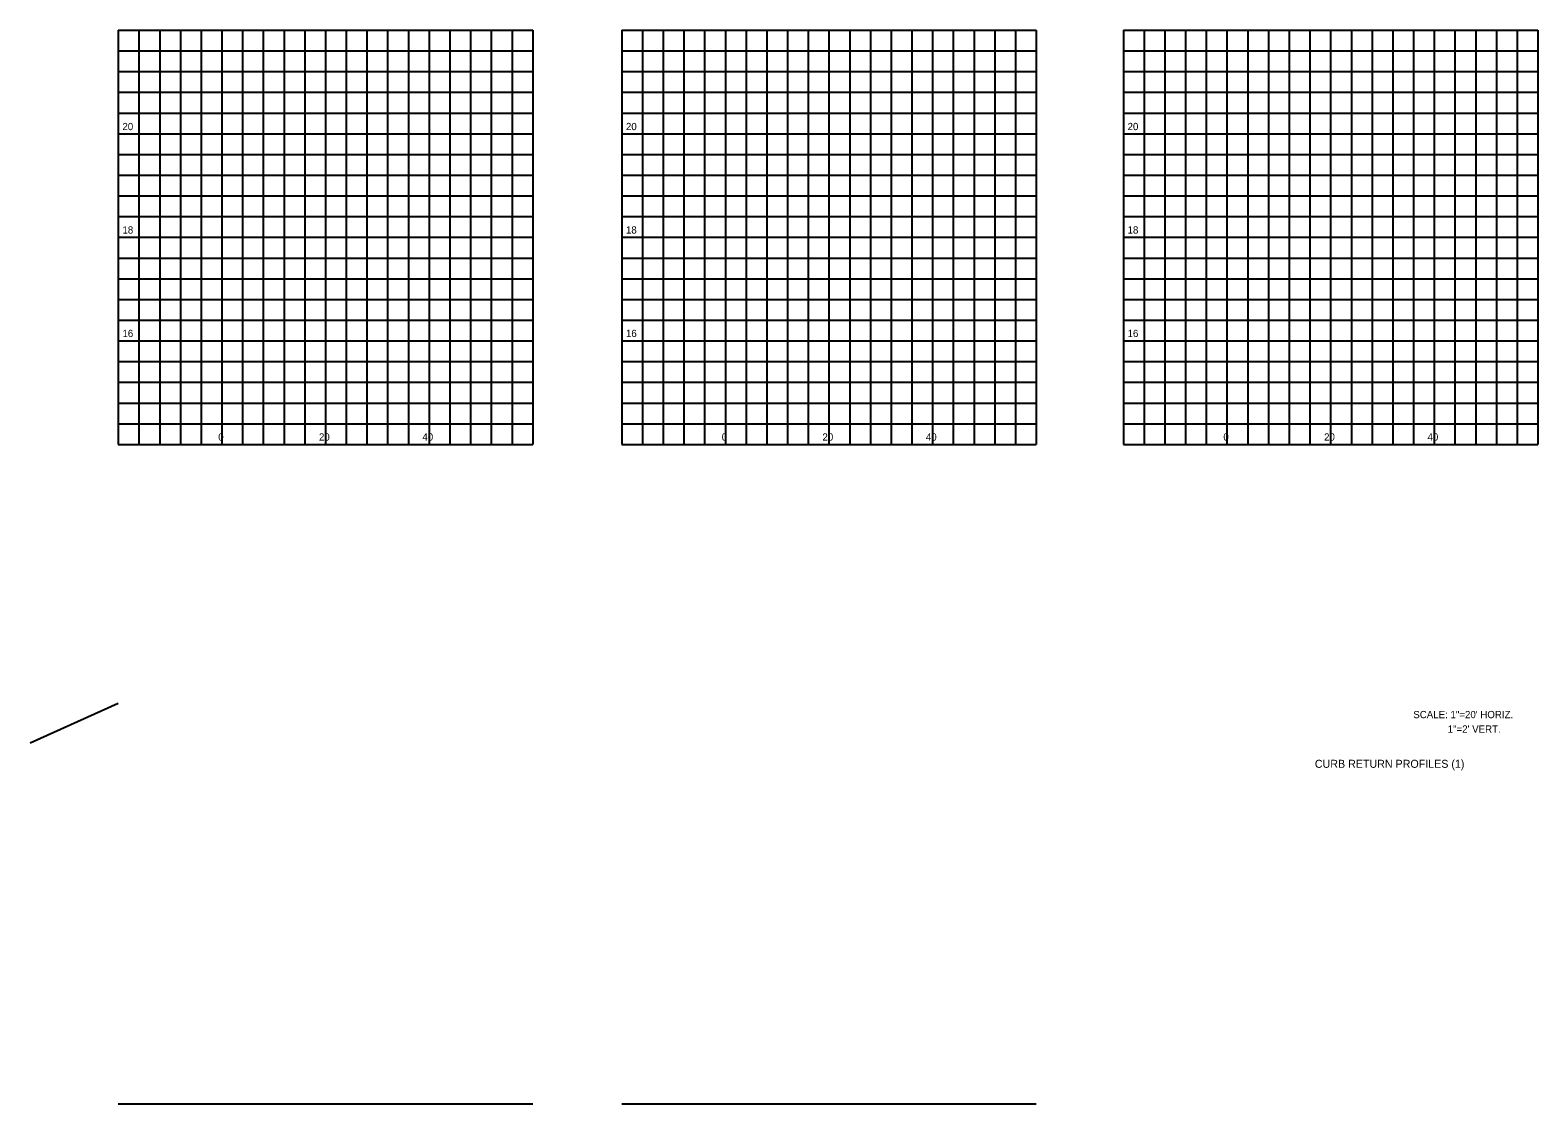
# Model space of a CAD drawing. Extents: x 127723 to 128378, y 21426 to 23736.
# Drawn here: x 127722.5 to 128013.5, y 23485.3 to 23692.7 of the extents above; entities that cross this region are included whole.
import ezdxf

# ---------------------------------------------------------------- set-up
doc = ezdxf.new("R2010")
doc.units = 0
for name, color, linetype in [('Default', 7, 'Continuous'), ('GroundCover', 7, 'Continuous'), ('Miscellaneous0', 7, 'Continuous'), ('SheetBorder_dp', 7, 'Continuous'), ('TextNotes', 7, 'Continuous')]:
    doc.layers.add(name, color=color, linetype=linetype)

msp = doc.modelspace()

# ---------------------------------------------------------------- linework, layer by layer
at = {"layer": 'Miscellaneous0'}
for p, q in [((127743.54, 23692.65), (127743.54, 23612.65)), ((127747.54, 23692.65), (127747.54, 23612.65)), ((127751.54, 23692.65), (127751.54, 23612.65)), ((127755.54, 23692.65), (127755.54, 23612.65)), ((127763.54, 23692.65), (127763.54, 23612.65)), ((127767.54, 23692.65), (127767.54, 23612.65)), ((127771.54, 23692.65), (127771.54, 23612.65)), ((127775.54, 23692.65), (127775.54, 23612.65)), ((127783.54, 23692.65), (127783.54, 23612.65)), ((127787.54, 23692.65), (127787.54, 23612.65)), ((127791.54, 23692.65), (127791.54, 23612.65)), ((127795.54, 23692.65), (127795.54, 23612.65)), ((127803.54, 23692.65), (127803.54, 23612.65)), ((127807.54, 23692.65), (127807.54, 23612.65)), ((127811.54, 23692.65), (127811.54, 23612.65)), ((127815.54, 23692.65), (127815.54, 23612.65)), ((127840.72, 23692.65), (127840.72, 23612.65)), ((127844.72, 23692.65), (127844.72, 23612.65)), ((127848.72, 23692.65), (127848.72, 23612.65)), ((127852.72, 23692.65), (127852.72, 23612.65)), ((127860.72, 23692.65), (127860.72, 23612.65)), ((127864.72, 23692.65), (127864.72, 23612.65)), ((127868.72, 23692.65), (127868.72, 23612.65)), ((127872.72, 23692.65), (127872.72, 23612.65)), ((127880.72, 23692.65), (127880.72, 23612.65)), ((127884.72, 23692.65), (127884.72, 23612.65)), ((127888.72, 23692.65), (127888.72, 23612.65)), ((127892.72, 23692.65), (127892.72, 23612.65)), ((127900.72, 23692.65), (127900.72, 23612.65)), ((127904.72, 23692.65), (127904.72, 23612.65)), ((127908.72, 23692.65), (127908.72, 23612.65)), ((127912.72, 23692.65), (127912.72, 23612.65)), ((127937.54, 23692.65), (127937.54, 23612.65)), ((127941.54, 23692.65), (127941.54, 23612.65)), ((127945.54, 23692.65), (127945.54, 23612.65)), ((127949.54, 23692.65), (127949.54, 23612.65)), ((127957.54, 23692.65), (127957.54, 23612.65)), ((127961.54, 23692.65), (127961.54, 23612.65)), ((127965.54, 23692.65), (127965.54, 23612.65)), ((127969.54, 23692.65), (127969.54, 23612.65)), ((127977.54, 23692.65), (127977.54, 23612.65)), ((127981.54, 23692.65), (127981.54, 23612.65)), ((127985.54, 23692.65), (127985.54, 23612.65)), ((127989.54, 23692.65), (127989.54, 23612.65)), ((127997.54, 23692.65), (127997.54, 23612.65)), ((128001.54, 23692.65), (128001.54, 23612.65)), ((128005.54, 23692.65), (128005.54, 23612.65)), ((128009.54, 23692.65), (128009.54, 23612.65)), ((127739.54, 23688.65), (127819.54, 23688.65)), ((127836.72, 23688.65), (127916.72, 23688.65)), ((127933.54, 23688.65), (128013.54, 23688.65)), ((127739.54, 23684.65), (127819.54, 23684.65)), ((127836.72, 23684.65), (127916.72, 23684.65)), ((127933.54, 23684.65), (128013.54, 23684.65)), ((127739.54, 23680.65), (127819.54, 23680.65)), ((127836.72, 23680.65), (127916.72, 23680.65)), ((127933.54, 23680.65), (128013.54, 23680.65)), ((127739.54, 23676.65), (127819.54, 23676.65)), ((127836.72, 23676.65), (127916.72, 23676.65)), ((127933.54, 23676.65), (128013.54, 23676.65)), ((127739.54, 23668.65), (127819.54, 23668.65)), ((127836.72, 23668.65), (127916.72, 23668.65)), ((127933.54, 23668.65), (128013.54, 23668.65)), ((127739.54, 23664.65), (127819.54, 23664.65)), ((127836.72, 23664.65), (127916.72, 23664.65)), ((127933.54, 23664.65), (128013.54, 23664.65)), ((127739.54, 23660.65), (127819.54, 23660.65)), ((127836.72, 23660.65), (127916.72, 23660.65)), ((127933.54, 23660.65), (128013.54, 23660.65)), ((127739.54, 23656.65), (127819.54, 23656.65)), ((127836.72, 23656.65), (127916.72, 23656.65)), ((127933.54, 23656.65), (128013.54, 23656.65)), ((127739.54, 23648.65), (127819.54, 23648.65)), ((127836.72, 23648.65), (127916.72, 23648.65)), ((127933.54, 23648.65), (128013.54, 23648.65)), ((127739.54, 23644.65), (127819.54, 23644.65)), ((127836.72, 23644.65), (127916.72, 23644.65)), ((127933.54, 23644.65), (128013.54, 23644.65)), ((127739.54, 23640.65), (127819.54, 23640.65)), ((127836.72, 23640.65), (127916.72, 23640.65)), ((127933.54, 23640.65), (128013.54, 23640.65)), ((127739.54, 23636.65), (127819.54, 23636.65)), ((127836.72, 23636.65), (127916.72, 23636.65)), ((127933.54, 23636.65), (128013.54, 23636.65)), ((127739.54, 23628.65), (127819.54, 23628.65)), ((127836.72, 23628.65), (127916.72, 23628.65)), ((127933.54, 23628.65), (128013.54, 23628.65)), ((127739.54, 23624.65), (127819.54, 23624.65)), ((127836.72, 23624.65), (127916.72, 23624.65)), ((127933.54, 23624.65), (128013.54, 23624.65)), ((127739.54, 23620.65), (127819.54, 23620.65)), ((127836.72, 23620.65), (127916.72, 23620.65)), ((127933.54, 23620.65), (128013.54, 23620.65)), ((127739.54, 23616.65), (127819.54, 23616.65)), ((127836.72, 23616.65), (127916.72, 23616.65)), ((127933.54, 23616.65), (128013.54, 23616.65))]:
    msp.add_line(p, q, dxfattribs=at)
at = {"layer": 'SheetBorder_dp'}
for p, q in [((127739.54, 23692.65), (127819.54, 23692.65)), ((127739.54, 23692.65), (127739.54, 23612.65)), ((127759.54, 23692.65), (127759.54, 23632.65)), ((127759.54, 23692.65), (127759.54, 23612.65)), ((127779.54, 23692.65), (127779.54, 23612.65)), ((127799.54, 23692.65), (127799.54, 23612.65)), ((127819.54, 23692.65), (127819.54, 23612.65)), ((127836.72, 23692.65), (127916.72, 23692.65)), ((127836.72, 23692.65), (127836.72, 23612.65)), ((127856.72, 23692.65), (127856.72, 23632.65)), ((127856.72, 23692.65), (127856.72, 23612.65)), ((127876.72, 23692.65), (127876.72, 23612.65)), ((127896.72, 23692.65), (127896.72, 23612.65)), ((127916.72, 23692.65), (127916.72, 23612.65)), ((127933.54, 23692.65), (128013.54, 23692.65)), ((127933.54, 23692.65), (127933.54, 23612.65)), ((127953.54, 23692.65), (127953.54, 23632.65)), ((127953.54, 23692.65), (127953.54, 23612.65)), ((127973.54, 23692.65), (127973.54, 23612.65)), ((127993.54, 23692.65), (127993.54, 23612.65)), ((128013.54, 23692.65), (128013.54, 23612.65)), ((127739.54, 23672.65), (127819.54, 23672.65)), ((127836.72, 23672.65), (127916.72, 23672.65)), ((127933.54, 23672.65), (128013.54, 23672.65)), ((127739.54, 23652.65), (127819.54, 23652.65)), ((127836.72, 23652.65), (127916.72, 23652.65)), ((127933.54, 23652.65), (128013.54, 23652.65)), ((127739.54, 23632.65), (127819.54, 23632.65)), ((127739.54, 23632.65), (127819.54, 23632.65)), ((127836.72, 23632.65), (127916.72, 23632.65)), ((127836.72, 23632.65), (127916.72, 23632.65)), ((127933.54, 23632.65), (128013.54, 23632.65)), ((127933.54, 23632.65), (128013.54, 23632.65)), ((127739.54, 23612.65), (127819.54, 23612.65)), ((127836.72, 23612.65), (127916.72, 23612.65)), ((127933.54, 23612.65), (128013.54, 23612.65)), ((127739.54, 23485.32), (127819.54, 23485.32)), ((127836.72, 23485.32), (127916.72, 23485.32))]:
    msp.add_line(p, q, dxfattribs=at)
at = {"layer": 'TextNotes'}
msp.add_line((127739.54, 23562.65), (127722.54, 23554.98), dxfattribs=at)

# ---------------------------------------------------------------- texts
at = {"layer": 'Default'}
msp.add_text('CURB RETURN PROFILES (1)', height=1.5418, dxfattribs=at).set_placement((127970.5, 23550.21))
at = {"layer": 'GroundCover'}
for s, p in [('20', (127740.35, 23673.34)), ('20', (127837.53, 23673.34)), ('20', (127934.35, 23673.34)), ('18', (127740.35, 23653.37)), ('18', (127837.53, 23653.37)), ('18', (127934.35, 23653.37)), ('16', (127740.35, 23633.39)), ('16', (127837.53, 23633.39)), ('16', (127934.35, 23633.39)), ('0', (127758.84, 23613.39)), ('20', (127778.28, 23613.39)), ('40', (127798.24, 23613.39)), ('0', (127856.02, 23613.39)), ('20', (127875.46, 23613.39)), ('40', (127895.42, 23613.39)), ('0', (127952.84, 23613.39)), ('20', (127972.28, 23613.39)), ('40', (127992.24, 23613.39)), ('SCALE: 1"=20\' HORIZ.', (127989.5, 23559.79)), ('  1"=2\' VERT.', (127995.1, 23556.99))]:
    msp.add_text(s, height=1.4, dxfattribs=at).set_placement(p)

doc.saveas('drawing.dxf')
